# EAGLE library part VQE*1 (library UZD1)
LED-Anzeige 2 7-Segment-Ziffern ±1.8.
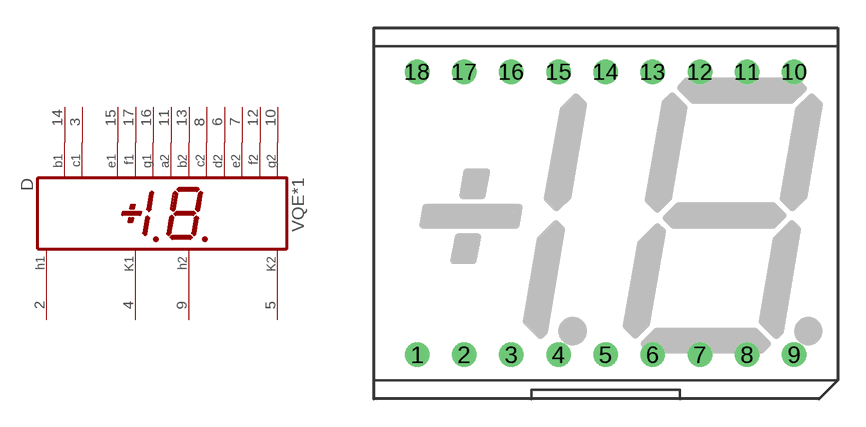
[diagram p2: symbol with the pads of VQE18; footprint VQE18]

Designator prefix D

## VQE1  [VQE18]
2  H1  pas
3  C1  pas
4  GK1  pas
5  GK2  pas
6  D2  pas
7  E2  pas
8  C2  pas
9  H2  pas
10  G2  pas
11  A2  pas
12  F2  pas
13  B2  pas
14  B1  pas
15  E1  pas
16  G1  pas
17  F1  pas

## Footprint VQE18 (pad centres in mm)
LED-Anzeige 12,7 mm Siebensegment ±1.8.
drill 0.813 round: 1 -10.16,-7.62; 2 -7.62,-7.62; 3 -5.08,-7.62; 4 -2.54,-7.62; 5 0,-7.62; 6 2.54,-7.62; 7 5.08,-7.62; 8 7.62,-7.62; 9 10.16,-7.62; 10 10.16,7.62; 11 7.62,7.62; 12 5.08,7.62; 13 2.54,7.62; 14 0,7.62; 15 -2.54,7.62; 16 -5.08,7.62; 17 -7.62,7.62; 18 -10.16,7.62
